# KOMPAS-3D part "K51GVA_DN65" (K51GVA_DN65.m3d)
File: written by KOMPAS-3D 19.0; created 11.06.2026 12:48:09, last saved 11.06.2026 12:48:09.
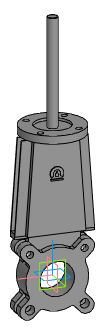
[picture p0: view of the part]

Document properties: Автор: Энергия; Полное имя файла: Z:\3.Личные\kachalov\001_3d для проектировщиков\2.6 Тип_K51GVA. Задвижка\_stp\_stp_K51GVA_DN50-DN1000_с фланцем\K51GVA_DN65.m3d

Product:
- Part/product: K51GVA_DN65

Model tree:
1. Операция без истории:1  (labels: K51GVA_DN65)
